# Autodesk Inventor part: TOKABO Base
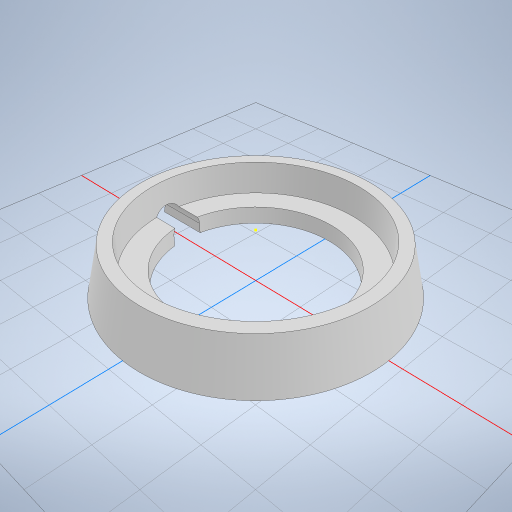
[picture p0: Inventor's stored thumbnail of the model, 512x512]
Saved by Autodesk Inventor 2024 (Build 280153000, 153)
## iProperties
Created: 2025-01
Part Number: TOKABO Base
Material: Generic
Document SubType Name: Modeling
Designer: samue
Density: 1 g/cm^3
Appearance: Default
Author: samue
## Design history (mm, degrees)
sketch "Sketch1"
  geometry: C1 r 55 at (0, 0); 1 further point
  constraints: 1 centre point, 1 coincident
  dimensions: "d0" = 110 diameter of C1
workplane "Work Plane1"
sketch "Sketch2"
  geometry: C1 r 50 at (0, 0); 1 further point
  constraints: 1 centre point, 1 coincident
  dimensions: "d2" = 100 diameter of C1
loft "Loft1" sketch "Sketch2" dims "d3" = 0, "d4" = 90 deg, "d5" = 0, "d6" = 90 deg
sketch "Sketch3"
  geometry: 1 further point
sketch "Sketch4"
  geometry: C1 r 45 at (0, 0); 1 further point
  constraints: 1 centre point, 1 coincident
  dimensions: "d7" = 90 diameter of C1
extrude "Extrusion1" cut sketch "Sketch4" distance "d8" = 13; taper "d9" = 0 deg
sketch "Sketch5"
  geometry: C1 r 35 at (0, 0); 1 further point
  constraints: 1 centre point, 1 coincident
  dimensions: "d10" = 70 diameter of C1
extrude "Extrusion2" cut sketch "Sketch5" distance "d11" = 7; taper "d12" = 0 deg
workplane "Work Plane2"
sketch "Sketch6"
  geometry: L1 (0, 0)-(4, 0); L2 (4, -6)-(-0.084, -6); L3 (4, 6)-(-0.084, 6); L4 (-0.084, -6)-(-0.084, 6); A1 r 6 centre (4, 0) between (4, -6) and (4, 6)
  constraints: 8 end point, 3 horizontal, 2 point on circle, 2 tangent, 1 centre point, 1 coincident, 1 parallel, 1 vertical
  dimensions: "d14" = 4 distance of L1.start L1.end; "d15" = 12 diameter of A1
extrude "Extrusion3" cut sketch "Sketch6" stored distance "d16" = 7; taper "d17" = 0 deg
body "Solid1"
other parameters: "d13" = -55
